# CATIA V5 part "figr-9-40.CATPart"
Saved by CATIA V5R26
Part number: Part1
Bounding box of the stored display mesh (mm): x -40 to 40, y -20 to 191.034, z 0 to 131.919
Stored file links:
  D:\_Deepak\CATIA\CATIA V5-6R2016_Deepak\Resources\Part files\Partfiles\c09_catia_v5_6r2016_prt\figr-9-40.CATPart
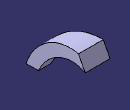
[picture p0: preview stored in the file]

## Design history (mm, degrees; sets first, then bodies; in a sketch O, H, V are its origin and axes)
Set1
  Plane1: type Normal, Curve Sketch2, RefPoint vertex of Sketch2
Body1 (main body)
  Sketch1 on xy-plane, origin (0, 0, 0), H (1, 0, 0), V (0, 1, 0)
    line L1 (20, 20) -> (20, -20)
    line L2 (20, -20) -> (-20, -20)
    line L3 (-20, -20) -> (-20, 20)
    line L4 (-20, 20) -> (20, 20)
    vertical: L1 V, L3 V
    horizontal: L2 H, L4 H
    equidistance: L1 L3 O, L2 L4 O
  Sketch2 on yz-plane, origin (0, 0, 0), H (0, 1, 0), V (0, 0, 1)
    spline S1 through (0, 0) (20, 60) (60, 80) (120, 90) (180, 110)
    point P1 (0, 0)
    coincidence: P1 O
  Sketch3 on Plane1, origin (0, 186.3865, 97.8327), H (1, 0, 0), V (0, -0.4648, 0.8854)
    point P1 (0, 13.7415)
    line L1 (40, 37.4831) -> (40, -10)
    line L2 (40, -10) -> (-40, -10)
    line L3 (-40, -10) -> (-40, 37.4831)
    line L4 (-40, 37.4831) -> (40, 37.4831)
    reference projected point E1 (0, 13.7415) from vertex of Sketch2
    coincidence: P1 V, P1 E1
    vertical: L1 V, L3 V
    horizontal: L2 H, L4 H
    equidistance: L1 L3 P1, L2 L4 P1
  Loft1: Sections (Sketch1; Sketch3)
